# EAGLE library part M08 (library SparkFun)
Header 8 Standard 8-pin 0.1" header. Use with straight break away headers (SKU : PType-HD), right angle break away headers (PType-HD-RightAngle), swiss pins (PType-30F), machine pins (PType-MP), and female headers (PType-FH). Molex polarized connector foot print use with SKU : Con-Hdr with associated crimp pins and housings.
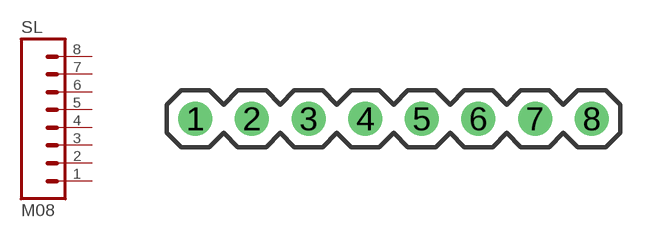
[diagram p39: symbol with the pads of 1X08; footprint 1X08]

Designator prefix SL

## M08  [1X08]
1  1  pas
2  2  pas
3  3  pas
4  4  pas
5  5  pas
6  6  pas
7  7  pas
8  8  pas

## Footprint 1X08 (pad centres in mm)
drill 1.016 round: 1 0,0; 2 2.54,0; 3 5.08,0; 4 7.62,0; 5 10.16,0; 6 12.7,0; 7 15.24,0; 8 17.78,0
